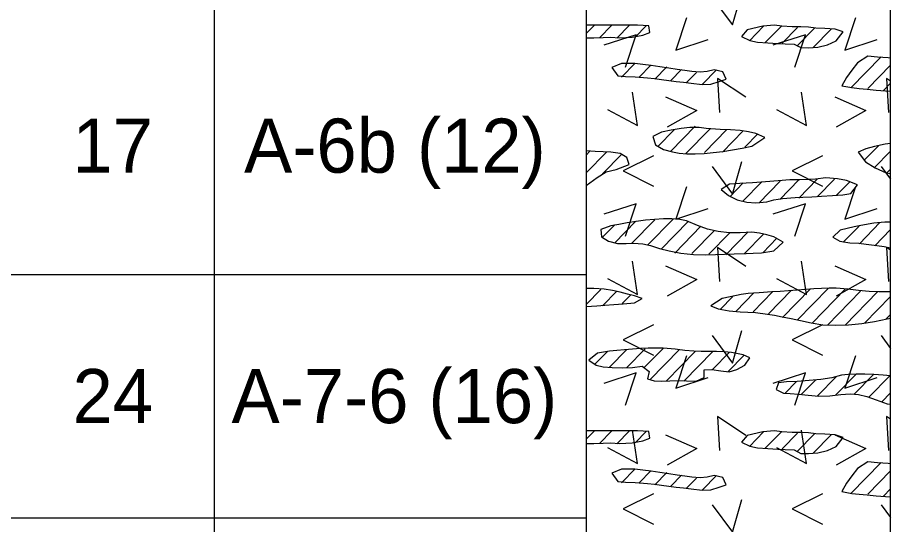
# Model space of a CAD drawing. Extents: x 0 to 0.833, y -0.323 to 0.608.
# Drawn here: x 0.7258 to 0.8333, y 0.3502 to 0.4127 of the extents above; entities that cross this region are included whole.
import ezdxf

# ---------------------------------------------------------------- set-up
doc = ezdxf.new("R2010")
doc.units = 0

msp = doc.modelspace()

# ---------------------------------------------------------------- linework, layer by layer
for points in [[(0, -0.32328), (0.83333, -0.32328), (0.83333, 0.60833), (0, 0.60833)], [(0.79583, 0.41018), (0.79676, 0.41017), (0.79792, 0.41019), (0.79882, 0.41023), (0.79992, 0.41018), (0.80151, 0.41023), (0.80282, 0.41048), (0.80367, 0.4108), (0.80354, 0.41164), (0.80216, 0.41173), (0.79583, 0.41173)], [(0.81822, 0.40953), (0.81944, 0.40947), (0.82033, 0.40943), (0.82145, 0.40937), (0.82229, 0.40895), (0.82324, 0.40891), (0.82438, 0.40901), (0.82555, 0.4093), (0.82662, 0.40981), (0.82749, 0.4109), (0.82651, 0.41121), (0.82524, 0.41131), (0.82413, 0.41137), (0.82324, 0.41148), (0.82226, 0.4115), (0.82121, 0.41152), (0.81995, 0.41161), (0.81902, 0.41173), (0.81761, 0.41159), (0.81566, 0.41114), (0.81496, 0.41031), (0.81598, 0.40982), (0.81695, 0.40964)], [(0.83305, 0.40768), (0.83171, 0.40779), (0.83054, 0.40789), (0.82925, 0.40707), (0.82857, 0.40616), (0.82792, 0.40527), (0.82735, 0.40424), (0.82858, 0.40402), (0.82945, 0.40392), (0.83045, 0.40382), (0.83155, 0.40373), (0.83272, 0.40363), (0.83333, 0.40358), (0.83333, 0.40767)], [(0.80066, 0.40538), (0.80188, 0.40537), (0.80339, 0.40524), (0.80423, 0.40515), (0.8051, 0.40504), (0.806, 0.40492), (0.80692, 0.4048), (0.80784, 0.40468), (0.80875, 0.40457), (0.81014, 0.40443), (0.81119, 0.40444), (0.81222, 0.40478), (0.81308, 0.40507), (0.81267, 0.40597), (0.8116, 0.40622), (0.81075, 0.40602), (0.80989, 0.40594), (0.80885, 0.40602), (0.80799, 0.40613), (0.80703, 0.40627), (0.806, 0.40644), (0.80492, 0.4066), (0.80384, 0.40676), (0.8028, 0.40689), (0.80182, 0.40698), (0.8002, 0.40699), (0.79901, 0.40652), (0.79974, 0.40548)], [(0.81233, 0.39887), (0.81063, 0.39899), (0.80977, 0.39912), (0.8086, 0.39913), (0.80755, 0.39899), (0.80632, 0.39879), (0.80513, 0.39854), (0.80403, 0.39802), (0.80436, 0.39696), (0.80536, 0.39639), (0.80647, 0.3961), (0.8073, 0.39595), (0.80824, 0.39587), (0.80926, 0.39586), (0.81035, 0.39591), (0.81149, 0.39601), (0.81267, 0.39616), (0.81386, 0.39635), (0.81506, 0.39656), (0.81625, 0.39679), (0.81783, 0.39787), (0.81673, 0.39837), (0.81585, 0.39857), (0.8148, 0.39873), (0.81361, 0.39883)], [(0.83265, 0.39706), (0.83136, 0.39675), (0.83028, 0.39647), (0.82934, 0.39608), (0.83026, 0.39488), (0.83142, 0.39412), (0.83279, 0.39354), (0.83333, 0.39344), (0.83333, 0.39715)], [(0.79583, 0.39196), (0.79719, 0.39295), (0.79831, 0.39365), (0.79951, 0.39392), (0.80111, 0.39453), (0.80086, 0.39541), (0.80002, 0.39589), (0.79889, 0.39608), (0.79791, 0.39611), (0.79694, 0.39617), (0.79583, 0.39625)], [(0.82537, 0.39291), (0.82408, 0.39276), (0.82319, 0.3927), (0.82214, 0.39267), (0.82091, 0.39264), (0.81947, 0.39254), (0.81792, 0.39242), (0.81632, 0.3923), (0.81475, 0.39221), (0.81348, 0.39211), (0.81247, 0.39147), (0.81337, 0.39071), (0.81444, 0.39021), (0.81561, 0.38992), (0.81675, 0.38981), (0.81807, 0.38993), (0.81896, 0.3902), (0.82003, 0.39035), (0.82157, 0.39047), (0.82253, 0.39053), (0.82362, 0.39058), (0.82483, 0.39064), (0.82618, 0.39071), (0.82745, 0.39082), (0.82842, 0.39099), (0.82927, 0.39205), (0.82791, 0.39257), (0.82679, 0.39277)], [(0.79885, 0.387), (0.79763, 0.38654), (0.79773, 0.38564), (0.79859, 0.38512), (0.7997, 0.38482), (0.80074, 0.38483), (0.80165, 0.38484), (0.80281, 0.38476), (0.80377, 0.38455), (0.80486, 0.3842), (0.80606, 0.38391), (0.80751, 0.38363), (0.80905, 0.38345), (0.81052, 0.38342), (0.81177, 0.38347), (0.81289, 0.38351), (0.81408, 0.38355), (0.81553, 0.38359), (0.81642, 0.38362), (0.81745, 0.38365), (0.81897, 0.38392), (0.82011, 0.38496), (0.81896, 0.38563), (0.8181, 0.38589), (0.81717, 0.38609), (0.81626, 0.38619), (0.81479, 0.38614), (0.81343, 0.38614), (0.8121, 0.38629), (0.8108, 0.38659), (0.80953, 0.38705), (0.8082, 0.3876), (0.80736, 0.38776), (0.8064, 0.38784), (0.80536, 0.38784), (0.80427, 0.38778), (0.80314, 0.38767), (0.80201, 0.38752), (0.8009, 0.38735), (0.79984, 0.38717)], [(0.83263, 0.38744), (0.83126, 0.38731), (0.82969, 0.38704), (0.82883, 0.38687), (0.82712, 0.38646), (0.82623, 0.38559), (0.82708, 0.3851), (0.82831, 0.38491), (0.82941, 0.38484), (0.83033, 0.38475), (0.83165, 0.38457), (0.83253, 0.38443), (0.83333, 0.38429), (0.83333, 0.38744)], [(0.79583, 0.37704), (0.79715, 0.37715), (0.79814, 0.37722), (0.79922, 0.3773), (0.80039, 0.37739), (0.80179, 0.37751), (0.80275, 0.37802), (0.80179, 0.37836), (0.80091, 0.37858), (0.80003, 0.3788), (0.79909, 0.379), (0.79803, 0.37917), (0.79677, 0.37927), (0.79583, 0.37925)], [(0.82816, 0.37479), (0.82978, 0.37496), (0.83137, 0.37521), (0.8329, 0.37552), (0.83333, 0.37563), (0.83333, 0.37887), (0.83295, 0.37884), (0.83188, 0.37886), (0.83071, 0.37891), (0.82938, 0.37901), (0.82807, 0.37918), (0.82662, 0.3793), (0.82576, 0.3793), (0.82484, 0.37928), (0.82387, 0.37923), (0.82286, 0.37916), (0.82182, 0.37908), (0.82077, 0.37899), (0.81973, 0.37891), (0.81872, 0.37884), (0.81715, 0.37874), (0.81579, 0.37865), (0.81491, 0.37852), (0.81357, 0.37824), (0.8126, 0.37803), (0.81121, 0.37711), (0.8121, 0.37675), (0.81345, 0.3765), (0.81479, 0.37641), (0.81668, 0.37631), (0.81818, 0.37611), (0.81905, 0.37596), (0.82, 0.37578), (0.82107, 0.37557), (0.82225, 0.37532), (0.82357, 0.37503), (0.82501, 0.3748), (0.82656, 0.37473)], [(0.79708, 0.36981), (0.79794, 0.36963), (0.79904, 0.36952), (0.80028, 0.36949), (0.80156, 0.36954), (0.80274, 0.36969), (0.80361, 0.36903), (0.80338, 0.36814), (0.80422, 0.36787), (0.80517, 0.36785), (0.80613, 0.3679), (0.8072, 0.36793), (0.80818, 0.3679), (0.80939, 0.36783), (0.81037, 0.3683), (0.81038, 0.36924), (0.8113, 0.3693), (0.81244, 0.36912), (0.81346, 0.36901), (0.81438, 0.36927), (0.81539, 0.36981), (0.81601, 0.37072), (0.81517, 0.3711), (0.81374, 0.37137), (0.81285, 0.37146), (0.81187, 0.37152), (0.81, 0.37152), (0.8091, 0.37154), (0.808, 0.37162), (0.80678, 0.37177), (0.8053, 0.3719), (0.80443, 0.37192), (0.80349, 0.3719), (0.80251, 0.37186), (0.80152, 0.3718), (0.80054, 0.37172), (0.79959, 0.37163), (0.7987, 0.37153), (0.79722, 0.37131), (0.79614, 0.37043)], [(0.83241, 0.36859), (0.83129, 0.36866), (0.83017, 0.36869), (0.8291, 0.36869), (0.82811, 0.36866), (0.82728, 0.36857), (0.82608, 0.36827), (0.82476, 0.36804), (0.8233, 0.36791), (0.82183, 0.36782), (0.82051, 0.36776), (0.81951, 0.36766), (0.81922, 0.3668), (0.82013, 0.36638), (0.82097, 0.36633), (0.822, 0.36623), (0.82318, 0.3661), (0.82448, 0.36601), (0.82584, 0.36604), (0.82719, 0.3662), (0.82836, 0.36627), (0.8294, 0.36619), (0.83043, 0.36595), (0.83156, 0.36556), (0.83291, 0.36507), (0.83333, 0.365), (0.83333, 0.36852)], [(0.79583, 0.36018), (0.79676, 0.36017), (0.79792, 0.36019), (0.79882, 0.36023), (0.79992, 0.36018), (0.80151, 0.36023), (0.80282, 0.36048), (0.80367, 0.3608), (0.80354, 0.36164), (0.80216, 0.36173), (0.79583, 0.36173)], [(0.81822, 0.35953), (0.81944, 0.35947), (0.82033, 0.35943), (0.82145, 0.35937), (0.82229, 0.35895), (0.82324, 0.35891), (0.82438, 0.35901), (0.82555, 0.3593), (0.82662, 0.35981), (0.82749, 0.3609), (0.82651, 0.36121), (0.82524, 0.36131), (0.82413, 0.36137), (0.82324, 0.36148), (0.82226, 0.3615), (0.82121, 0.36152), (0.81995, 0.36161), (0.81902, 0.36173), (0.81761, 0.36159), (0.81566, 0.36114), (0.81496, 0.36031), (0.81598, 0.35982), (0.81695, 0.35964)], [(0.83305, 0.35768), (0.83171, 0.35779), (0.83054, 0.35789), (0.82925, 0.35707), (0.82857, 0.35616), (0.82792, 0.35527), (0.82735, 0.35424), (0.82858, 0.35402), (0.82945, 0.35392), (0.83045, 0.35382), (0.83155, 0.35373), (0.83272, 0.35363), (0.83333, 0.35358), (0.83333, 0.35767)], [(0.80066, 0.35538), (0.80188, 0.35537), (0.80339, 0.35524), (0.80423, 0.35515), (0.8051, 0.35504), (0.806, 0.35492), (0.80692, 0.3548), (0.80784, 0.35468), (0.80875, 0.35457), (0.81014, 0.35443), (0.81119, 0.35444), (0.81222, 0.35478), (0.81308, 0.35507), (0.81267, 0.35597), (0.8116, 0.35622), (0.81075, 0.35602), (0.80989, 0.35594), (0.80885, 0.35602), (0.80799, 0.35613), (0.80703, 0.35627), (0.806, 0.35644), (0.80492, 0.3566), (0.80384, 0.35676), (0.8028, 0.35689), (0.80182, 0.35698), (0.8002, 0.35699), (0.79901, 0.35652), (0.79974, 0.35548)]]:
    msp.add_lwpolyline(points, close=True)
for points in [[(0.75, 0.55417), (0.75, -0.28575)], [(0.75, 0.55417), (0.75, -0.28575)], [(0.79583, 0.55417), (0.79583, -0.28575)], [(0.83333, -0.28575), (0.83333, 0.50165)], [(0.81134, 0.41512), (0.81384, 0.41175), (0.81503, 0.41575)], [(0.80818, 0.41263), (0.80687, 0.40863), (0.81087, 0.40994)], [(0.82901, 0.41263), (0.8277, 0.40863), (0.8317, 0.40994)], [(0.79583, 0.4107), (0.79681, 0.4117)], [(0.79898, 0.41171), (0.79747, 0.41017)], [(0.80116, 0.41173), (0.79959, 0.41013)], [(0.80328, 0.41169), (0.80188, 0.41026)], [(0.8177, 0.41159), (0.81596, 0.40981)], [(0.81988, 0.41161), (0.81785, 0.40953)], [(0.82185, 0.41142), (0.81997, 0.40949)], [(0.824, 0.41141), (0.82178, 0.40913)], [(0.82601, 0.41125), (0.82378, 0.40897)], [(0.80069, 0.40655), (0.802, 0.41055), (0.798, 0.40924)], [(0.82152, 0.40655), (0.82284, 0.41055), (0.81884, 0.40924)], [(0.83217, 0.40781), (0.82844, 0.40399)], [(0.80188, 0.40703), (0.8002, 0.40531)], [(0.8038, 0.40679), (0.80237, 0.40532)], [(0.83333, 0.40679), (0.83052, 0.40391)], [(0.80575, 0.40657), (0.80429, 0.40508)], [(0.80758, 0.40624), (0.80627, 0.40489)], [(0.80941, 0.4059), (0.80816, 0.40462)], [(0.81188, 0.40621), (0.81016, 0.40446)], [(0.81551, 0.40283), (0.81201, 0.40514), (0.81226, 0.40095)], [(0.83333, 0.40457), (0.83245, 0.40367)], [(0.83333, 0.40482), (0.83284, 0.40514), (0.83309, 0.40095)], [(0.79847, 0.40134), (0.80215, 0.39934), (0.80153, 0.40347)], [(0.8193, 0.40134), (0.82299, 0.39934), (0.82236, 0.40347)], [(0.80562, 0.40289), (0.80946, 0.40121), (0.80581, 0.39914)], [(0.82645, 0.40289), (0.83029, 0.40121), (0.82664, 0.39914)], [(0.80626, 0.39619), (0.80928, 0.39928)], [(0.80465, 0.39675), (0.80667, 0.39883)], [(0.80809, 0.39585), (0.81111, 0.39895)], [(0.81041, 0.39602), (0.81318, 0.39885)], [(0.81264, 0.39609), (0.81518, 0.39869)], [(0.81536, 0.39667), (0.81699, 0.39833)], [(0.7963, 0.39621), (0.79583, 0.39572)], [(0.79834, 0.39608), (0.79583, 0.39351)], [(0.8301, 0.39509), (0.83184, 0.39687)], [(0.83131, 0.39412), (0.83333, 0.39619)], [(0.79786, 0.39338), (0.80023, 0.39581)], [(0.80412, 0.39563), (0.80038, 0.39376), (0.80412, 0.39188)], [(0.81134, 0.39429), (0.81384, 0.39091), (0.81503, 0.39491)], [(0.82496, 0.39563), (0.82121, 0.39376), (0.82496, 0.39188)], [(0.83217, 0.39429), (0.83333, 0.39273)], [(0.83285, 0.39349), (0.83333, 0.39398)], [(0.8197, 0.39025), (0.82203, 0.39265)], [(0.82202, 0.39042), (0.8243, 0.39275)], [(0.82431, 0.39055), (0.82644, 0.39274)], [(0.80818, 0.3918), (0.80687, 0.3878), (0.81087, 0.38911)], [(0.81519, 0.39228), (0.81354, 0.39058)], [(0.81514, 0.39001), (0.81748, 0.39241)], [(0.81709, 0.3898), (0.81974, 0.39251)], [(0.82663, 0.39071), (0.82834, 0.39247)], [(0.82901, 0.3918), (0.8277, 0.3878), (0.8317, 0.38911)], [(0.80069, 0.38572), (0.802, 0.38972), (0.798, 0.38841)], [(0.82152, 0.38572), (0.82284, 0.38972), (0.81884, 0.38841)], [(0.79933, 0.38487), (0.80195, 0.38756)], [(0.80142, 0.3848), (0.8043, 0.38775)], [(0.80653, 0.38783), (0.8034, 0.38461)], [(0.80506, 0.3841), (0.8084, 0.38752)], [(0.83203, 0.38739), (0.82949, 0.38479)], [(0.79938, 0.38713), (0.79786, 0.38558)], [(0.80997, 0.38693), (0.80675, 0.38362)], [(0.81164, 0.38642), (0.80884, 0.38356)], [(0.81303, 0.38342), (0.81579, 0.38625)], [(0.82751, 0.38498), (0.82945, 0.38696)], [(0.83138, 0.38452), (0.83333, 0.38652)], [(0.81353, 0.38614), (0.81094, 0.38349)], [(0.81534, 0.38358), (0.81768, 0.38597)], [(0.8176, 0.38368), (0.81934, 0.38547)], [(0.81551, 0.38199), (0.81201, 0.38431), (0.81226, 0.38012)], [(0.83333, 0.38398), (0.83284, 0.38431), (0.83309, 0.38012)], [(0.83333, 0.3843), (0.83333, 0.38431)], [(0.79847, 0.38051), (0.80215, 0.37851), (0.80153, 0.38264)], [(0.80562, 0.38206), (0.80946, 0.38037), (0.80581, 0.37831)], [(0.8193, 0.38051), (0.82299, 0.37851), (0.82236, 0.38264)], [(0.82645, 0.38206), (0.83029, 0.38037), (0.82664, 0.37831)], [(0.725, 0.381), (0.75, 0.381)], [(0.75, 0.381), (0.79583, 0.381)], [(0.79765, 0.37915), (0.79583, 0.37728)], [(0.7996, 0.37894), (0.79786, 0.37715)], [(0.8143, 0.37648), (0.8165, 0.37873)], [(0.8164, 0.37641), (0.81879, 0.37886)], [(0.81829, 0.37613), (0.82114, 0.37905)], [(0.82004, 0.37571), (0.82346, 0.37922)], [(0.82569, 0.37929), (0.82184, 0.37535)], [(0.82775, 0.37919), (0.8237, 0.37505)], [(0.82964, 0.37892), (0.82557, 0.37474)], [(0.83173, 0.37885), (0.82774, 0.37476)], [(0.8013, 0.37846), (0.80027, 0.37741)], [(0.81392, 0.3783), (0.81235, 0.37669)], [(0.83333, 0.37827), (0.83012, 0.37498)], [(0.83281, 0.37552), (0.83333, 0.37606)], [(0.80412, 0.3748), (0.80038, 0.37292), (0.80412, 0.37105)], [(0.82496, 0.3748), (0.82121, 0.37292), (0.82496, 0.37105)], [(0.81134, 0.37346), (0.81384, 0.37008), (0.81503, 0.37408)], [(0.83217, 0.37346), (0.83333, 0.37189)], [(0.79844, 0.37149), (0.79691, 0.36992)], [(0.79871, 0.36955), (0.80085, 0.37174)], [(0.80083, 0.36951), (0.80311, 0.37185)], [(0.80534, 0.37192), (0.80299, 0.36951)], [(0.80367, 0.368), (0.80732, 0.37174)], [(0.80571, 0.36788), (0.80924, 0.37149)], [(0.81142, 0.37151), (0.80785, 0.36786)], [(0.81141, 0.36929), (0.81348, 0.37141)], [(0.80818, 0.37097), (0.80687, 0.36697), (0.81087, 0.36828)], [(0.81528, 0.37104), (0.81331, 0.36903)], [(0.82901, 0.37097), (0.8277, 0.36697), (0.8317, 0.36828)], [(0.80069, 0.36489), (0.802, 0.36889), (0.798, 0.36757)], [(0.82152, 0.36489), (0.82284, 0.36889), (0.81884, 0.36757)], [(0.82233, 0.36619), (0.82408, 0.36798)], [(0.82433, 0.36602), (0.82666, 0.36841)], [(0.82909, 0.36869), (0.82656, 0.3661)], [(0.82885, 0.36623), (0.83122, 0.36866)], [(0.83325, 0.36852), (0.83065, 0.36586)], [(0.82035, 0.36637), (0.82176, 0.36782)], [(0.83333, 0.3664), (0.83227, 0.36531)], [(0.81551, 0.36116), (0.81201, 0.36347), (0.81226, 0.35928)], [(0.83333, 0.36315), (0.83284, 0.36347), (0.83309, 0.35928)], [(0.79583, 0.3607), (0.79681, 0.3617)], [(0.79898, 0.36172), (0.79747, 0.36017)], [(0.79847, 0.35968), (0.80215, 0.35768), (0.80153, 0.3618)], [(0.80116, 0.36173), (0.79959, 0.36013)], [(0.80328, 0.36169), (0.80188, 0.36026)], [(0.8177, 0.36159), (0.81596, 0.35981)], [(0.81988, 0.36161), (0.81785, 0.35953)], [(0.8193, 0.35968), (0.82299, 0.35768), (0.82236, 0.3618)], [(0.80562, 0.36122), (0.80946, 0.35954), (0.80581, 0.35748)], [(0.82185, 0.36142), (0.81997, 0.35949)], [(0.824, 0.36141), (0.82178, 0.35913)], [(0.82601, 0.36125), (0.82378, 0.35897)], [(0.82645, 0.36122), (0.83029, 0.35954), (0.82664, 0.35748)], [(0.83217, 0.35781), (0.82844, 0.35399)], [(0.80188, 0.35703), (0.8002, 0.35531)], [(0.8038, 0.35679), (0.80237, 0.35532)], [(0.80575, 0.35657), (0.80429, 0.35508)], [(0.80758, 0.35624), (0.80627, 0.35489)], [(0.81188, 0.35621), (0.81016, 0.35446)], [(0.83333, 0.35679), (0.83052, 0.35391)], [(0.80941, 0.3559), (0.80816, 0.35462)], [(0.80412, 0.35396), (0.80038, 0.35209), (0.80412, 0.35021)], [(0.82496, 0.35396), (0.82121, 0.35209), (0.82496, 0.35021)], [(0.83333, 0.35457), (0.83245, 0.35367)], [(0.81134, 0.35262), (0.81384, 0.34925), (0.81503, 0.35325)], [(0.83217, 0.35262), (0.83333, 0.35106)], [(0.725, 0.35101), (0.75, 0.35101)], [(0.75, 0.35101), (0.79583, 0.35101)]]:
    msp.add_lwpolyline(points)

# ---------------------------------------------------------------- texts
for s, p in [('17', (0.73253, 0.39354)), ('A-6b (12)', (0.75368, 0.39354)), ('24', (0.73255, 0.36267)), ('A-7-6 (16)', (0.75213, 0.36267))]:
    msp.add_text(s, height=0.006667).set_placement(p)

doc.saveas('drawing.dxf')
